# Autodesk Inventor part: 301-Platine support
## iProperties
Author: Philippe
Shininess: 20.0
Angle Display Precision: 2
Document Length Units: 11269
Document Angle Units: 11283
Document Time Units: 11279
Document Mass Units: 11290
Document Length Units Precision: 3
Document Angle Units Precision: 2
Compacted: False
PropertySet Name: _Private Model Information
Created: 2001-12
Part Number: 301-Platine support
Material: Par défaut
Document SubType Name: Modélisation
Designer: Philippe
Control State: 0
Master: False
Checked Out: False
PropertySet Name: Design Tracking Control
Density: 0.0
Volumn: 0.0
Area: 0.0
PropertySet Name: Model Information
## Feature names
1. Extrusion1
2. Extrusion3
3. Perçage1 [Hole]
4. Réseau rectangulaire1 [Rectangular Pattern]
5. Perçage2 [Hole]
6. Réseau rectangulaire2 [Rectangular Pattern]
7. Perçage3 [Hole]
